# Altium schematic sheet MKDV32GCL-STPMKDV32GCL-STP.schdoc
size 127 x 101 mm
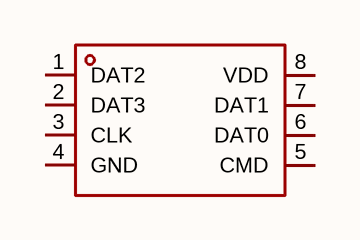
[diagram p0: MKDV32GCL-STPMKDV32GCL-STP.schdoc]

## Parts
U?  mkdv32gcl-stp  [LGA-8_L6.0-W8.0-P1.27-TL]  (value not drawn)

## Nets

Not connected (* = marked no-connect by the designer): U? 1(DAT2) 2(DAT3) 3(CLK) 4(GND) 5(CMD) 6(DAT0) 7(DAT1) 8(VDD)

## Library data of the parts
U? = mkdv32gcl-stp: 存储容量:32Gbit;时钟频率(fc):50MHz;工作电压:2.7V~3.6V;; Manufacturer: MK(米客方德); AddInBom: yes; ModelId: 1f88d973af574684b0007f41a35ee8d9; ModelName: LGA-8_L6.0-W8.0-H0.8-P1.27; ModelTransform: 314.96,236.22,0,0,0,0,0,0.005,0; Memory Size: 32Gbit; Interface: SD接口；SPI; Clock Frequency: 50MHz; Standby Supply Current: 250uA; Program / Erase Cycles: 5千次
